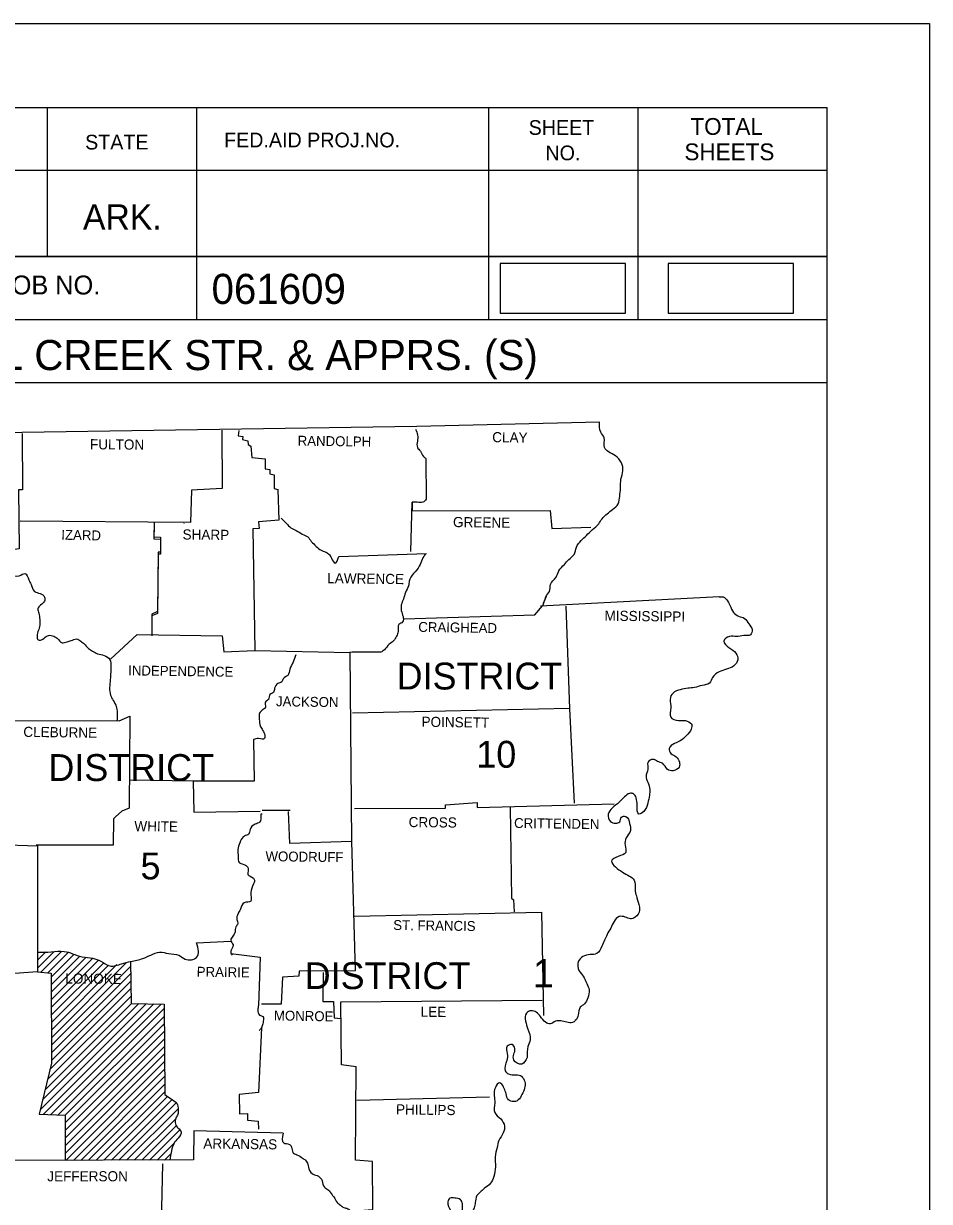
# Model space of a CAD drawing. Extents: x 1367863 to 1368197, y 380048 to 380261.
# Drawn here: x 1368154.6 to 1368196.7, y 380206.7 to 380261.4 of the extents above; entities that cross this region are included whole.
import ezdxf

# ---------------------------------------------------------------- set-up
doc = ezdxf.new("R2010")
doc.units = 0
for name, color, linetype in [('R_Border', 7, 'Continuous'), ('R_Dimension', 7, 'Continuous'), ('R_No Plot', 7, 'Continuous')]:
    doc.layers.add(name, color=color, linetype=linetype)

msp = doc.modelspace()

# ---------------------------------------------------------------- linework, layer by layer
at = {"layer": 'R_Border'}
for p, q in [((1367875.8, 380257.536), (1368191.969, 380257.536)), ((1368155.71, 380257.536), (1368155.71, 380250.596)), ((1368162.65, 380257.536), (1368162.65, 380247.657)), ((1368176.229, 380257.536), (1368176.229, 380247.657)), ((1368183.169, 380257.536), (1368183.169, 380247.657)), ((1368191.969, 380052.084), (1368191.969, 380257.536)), ((1368191.969, 380254.596), (1368148.87, 380254.596)), ((1368191.969, 380254.616), (1368191.969, 380254.616)), ((1368191.969, 380250.596), (1368148.87, 380250.596)), ((1368151.83, 380250.596), (1368191.969, 380250.596)), ((1368191.969, 380247.657), (1368109.712, 380247.657)), ((1368148.87, 380244.737), (1368191.969, 380244.737)), ((1368173.305, 380241.212), (1368173.325, 380239.319)), ((1368178.784, 380234.487), (1368178.924, 380234.806)), ((1368178.754, 380234.357), (1368178.884, 380234.766)), ((1368165.694, 380224.863), (1368166.999, 380224.863))]:
    msp.add_line(p, q, dxfattribs=at)
for points in [[(1368176.759, 380247.97), (1368182.592, 380247.97), (1368182.592, 380250.28), (1368176.759, 380250.28)], [(1368184.57, 380247.97), (1368190.404, 380247.97), (1368190.404, 380250.28), (1368184.57, 380250.28)]]:
    msp.add_lwpolyline(points, close=True, dxfattribs=at)
for points in [[(1368121.261, 380242.407), (1368138.984, 380242.397), (1368154.536, 380242.437), (1368172.886, 380242.716), (1368181.384, 380242.915)], [(1368163.821, 380242.527), (1368163.841, 380239.817), (1368162.416, 380239.737), (1368162.376, 380238.243), (1368154.446, 380238.293)], [(1368164.608, 380242.517), (1368164.578, 380242.258), (1368164.797, 380242.228), (1368164.787, 380242.088), (1368165.036, 380242.038), (1368165.056, 380241.859), (1368165.175, 380241.789), (1368165.215, 380241.261), (1368165.833, 380241.192), (1368165.833, 380240.723), (1368166.062, 380240.694), (1368166.062, 380240.504), (1368166.261, 380240.454), (1368166.251, 380239.817), (1368166.431, 380239.777), (1368166.471, 380238.342), (1368165.534, 380238.263), (1368165.554, 380237.954), (1368165.265, 380237.944), (1368165.365, 380232.285), (1368169.778, 380232.186), (1368169.858, 380223.399), (1368166.979, 380223.319), (1368166.919, 380224.803)], [(1368154.536, 380242.367), (1368154.556, 380239.757), (1368154.376, 380239.747), (1368154.406, 380237.017), (1368153.639, 380236.908), (1368153.699, 380236.171), (1368153.968, 380235.832), (1368153.948, 380234.975), (1368152.453, 380234.915), (1368152.404, 380233.58), (1368151.039, 380233.531), (1368150.979, 380231.917), (1368151.049, 380231.777), (1368151.089, 380229.197), (1368153.43, 380229.037), (1368153.4, 380223.269), (1368155.263, 380223.209), (1368155.263, 380217.342), (1368153.788, 380217.232), (1368153.679, 380215.937), (1368151.218, 380215.927)], [(1368172.617, 380236.888), (1368172.677, 380239.179), (1368172.677, 380238.771), (1368179.083, 380238.801), (1368179.173, 380237.954), (1368180.976, 380238.014)], [(1368160.682, 380238.213), (1368160.663, 380237.575), (1368160.971, 380237.555), (1368160.981, 380236.858), (1368160.872, 380236.858), (1368160.832, 380234.098), (1368160.573, 380233.979), (1368160.573, 380233.062)], [(1368160.682, 380238.113), (1368160.663, 380237.476), (1368160.971, 380237.456), (1368160.981, 380236.758), (1368160.872, 380236.758), (1368160.832, 380233.999), (1368160.573, 380233.889), (1368160.573, 380232.963)], [(1368162.057, 380238.193), (1368162.067, 380238.203)], [(1368169.26, 380236.649), (1368173.335, 380236.788)], [(1368172.289, 380233.75), (1368178.376, 380233.949), (1368178.734, 380234.367)], [(1368186.953, 380234.776), (1368178.635, 380234.347)], [(1368179.81, 380234.347), (1368179.99, 380229.595), (1368180.209, 380225.182)], [(1368158.65, 380231.887), (1368159.895, 380233.022), (1368163.841, 380232.963), (1368163.92, 380232.225), (1368165.355, 380232.285)], [(1368171.213, 380232.206), (1368169.878, 380232.206), (1368169.778, 380232.186)], [(1368179.99, 380229.595), (1368169.898, 380229.366)], [(1368153.43, 380229.037), (1368159.059, 380229.008), (1368159.547, 380229.237), (1368159.517, 380224.953), (1368159.178, 380224.813), (1368158.889, 380224.554), (1368158.79, 380224.465), (1368158.78, 380223.229), (1368155.193, 380223.229)], [(1368165.305, 380228.141), (1368165.335, 380226.218), (1368162.486, 380226.208), (1368159.557, 380226.258)], [(1368162.486, 380226.208), (1368162.525, 380224.764), (1368165.604, 380224.823)], [(1368169.987, 380224.933), (1368174.221, 380224.953), (1368174.231, 380225.112), (1368175.696, 380225.212), (1368175.696, 380224.983), (1368182.072, 380225.162)], [(1368177.23, 380224.983), (1368177.29, 380220.769), (1368177.389, 380220.699), (1368177.419, 380220.131)], [(1368165.694, 380224.684), (1368165.634, 380224.674)], [(1368169.858, 380223.399), (1368170.017, 380217.391), (1368167.417, 380217.381), (1368167.407, 380217.142), (1368166.65, 380217.093), (1368166.58, 380215.847), (1368165.664, 380215.847)], [(1368169.987, 380219.942), (1368178.685, 380220.121)], [(1368178.685, 380220.121), (1368178.774, 380215.319)], [(1368162.655, 380218.696), (1368164.249, 380218.776)], [(1368159.587, 380217.84), (1368159.606, 380215.877), (1368161.151, 380215.847), (1368161.171, 380211.643)], [(1368164.249, 380218.198), (1368165.614, 380218.029), (1368165.534, 380215.787)], [(1368155.263, 380217.342), (1368155.891, 380217.292), (1368155.91, 380213.108), (1368155.333, 380210.727), (1368156.548, 380210.677), (1368156.538, 380208.583)], [(1368168.533, 380217.322), (1368168.523, 380215.967), (1368169.021, 380215.967), (1368169.041, 380215.21), (1368169.36, 380215.18)], [(1368169.987, 380206.243), (1368170.844, 380206.303), (1368170.834, 380208.525), (1368170.037, 380208.585), (1368170.077, 380212.928), (1368169.39, 380213.028), (1368169.36, 380215.957), (1368178.714, 380216.027)], [(1368165.664, 380214.741), (1368165.524, 380211.743), (1368164.628, 380211.643), (1368164.648, 380210.746), (1368165.016, 380210.766), (1368165.026, 380210.458), (1368165.514, 380210.398), (1368165.524, 380210.039)], [(1368170.097, 380211.384), (1368176.274, 380211.543)], [(1368166.67, 380209.84), (1368162.525, 380209.949), (1368162.506, 380208.604), (1368154.117, 380208.575)], [(1368161.071, 380208.425), (1368160.981, 380204.301), (1368162.506, 380204.171)]]:
    msp.add_lwpolyline(points, dxfattribs=at)
for points in [[(1368172.827, 380242.576), (1368172.926, 380242.297), (1368172.916, 380242.009), (1368172.916, 380241.73), (1368173.056, 380241.55), (1368173.195, 380241.311), (1368173.305, 380241.212)], [(1368178.874, 380234.716), (1368178.884, 380234.766), (1368179.053, 380235.025), (1368179.103, 380235.354), (1368179.362, 380235.692), (1368179.492, 380235.991), (1368179.751, 380236.29), (1368179.95, 380236.509), (1368180.199, 380236.748), (1368180.308, 380237.087), (1368180.538, 380237.396), (1368180.777, 380237.635), (1368181.056, 380237.904), (1368181.345, 380238.173), (1368181.504, 380238.412), (1368181.733, 380238.641), (1368181.992, 380238.841), (1368182.251, 380239.109), (1368182.321, 380239.448), (1368182.361, 380239.827), (1368182.381, 380240.255), (1368182.47, 380240.634), (1368182.401, 380241.012), (1368182.122, 380241.331), (1368181.803, 380241.52), (1368181.614, 380241.72), (1368181.594, 380242.178), (1368181.444, 380242.437), (1368181.384, 380242.915)], [(1368173.325, 380239.319), (1368173.175, 380239.179), (1368172.906, 380239.179), (1368172.677, 380239.179)], [(1368166.59, 380238.442), (1368166.829, 380238.193), (1368167.038, 380237.984), (1368167.278, 380237.864), (1368167.566, 380237.695), (1368167.816, 380237.565), (1368167.985, 380237.356), (1368168.214, 380237.127), (1368168.443, 380236.948), (1368168.802, 380236.768), (1368168.921, 380236.579), (1368169.091, 380236.35), (1368169.26, 380236.649)], [(1368173.295, 380236.778), (1368173.135, 380236.519), (1368173.006, 380236.21), (1368172.737, 380235.862), (1368172.538, 380235.513), (1368172.508, 380235.284), (1368172.358, 380234.985), (1368172.269, 380234.676), (1368172.169, 380234.407), (1368172.169, 380234.138), (1368172.249, 380233.859), (1368172.229, 380233.61), (1368172.06, 380233.491), (1368172.02, 380233.172), (1368171.95, 380232.953), (1368171.81, 380232.734), (1368171.601, 380232.574), (1368171.382, 380232.315), (1368171.213, 380232.206)], [(1368153.968, 380235.832), (1368154.406, 380235.762), (1368154.665, 380235.862), (1368154.854, 380235.573), (1368154.954, 380235.354), (1368155.113, 380235.035), (1368155.382, 380234.935), (1368155.582, 380234.766), (1368155.582, 380234.577), (1368155.402, 380234.397), (1368155.273, 380234.228), (1368155.313, 380234.019), (1368155.362, 380233.73), (1368155.362, 380233.461), (1368155.293, 380233.202), (1368155.233, 380232.973), (1368155.293, 380232.783), (1368155.502, 380232.813), (1368155.721, 380232.973), (1368155.95, 380232.973), (1368156.169, 380232.853), (1368156.399, 380232.644), (1368156.628, 380232.694), (1368156.817, 380232.743), (1368157.076, 380232.823), (1368157.265, 380232.724), (1368157.425, 380232.594), (1368157.624, 380232.385), (1368157.813, 380232.255), (1368158.052, 380232.136), (1368158.351, 380232.056), (1368158.62, 380231.867), (1368158.67, 380231.548), (1368158.66, 380231.279), (1368158.64, 380230.94), (1368158.61, 380230.562), (1368158.65, 380230.203), (1368158.77, 380229.964), (1368158.919, 380229.675), (1368158.959, 380229.416), (1368158.949, 380228.998)], [(1368186.953, 380234.776), (1368187.073, 380234.786), (1368187.442, 380234.387), (1368187.611, 380234.059), (1368187.85, 380233.879), (1368188.129, 380233.78), (1368188.328, 380233.521), (1368188.478, 380233.252), (1368188.398, 380233.012), (1368188.089, 380232.983), (1368187.75, 380232.933), (1368187.422, 380232.943), (1368187.163, 380232.724), (1368187.402, 380232.425), (1368187.721, 380232.156), (1368187.81, 380231.857), (1368187.631, 380231.568), (1368187.282, 380231.418), (1368186.943, 380231.289), (1368186.635, 380231.03), (1368186.495, 380230.771), (1368186.156, 380230.661), (1368185.798, 380230.562), (1368185.499, 380230.532), (1368185.14, 380230.462), (1368184.802, 380230.303), (1368184.662, 380230.014), (1368184.702, 380229.615), (1368184.692, 380229.187), (1368185.061, 380229.037), (1368185.379, 380229.028), (1368185.678, 380228.868)], [(1368167.268, 380232.086), (1368167.138, 380231.747), (1368166.989, 380231.418), (1368166.889, 380231.13), (1368166.68, 380230.97), (1368166.61, 380230.821), (1368166.431, 380230.751), (1368166.281, 380230.532), (1368166.222, 380230.333), (1368166.062, 380230.243), (1368165.992, 380230.004), (1368165.843, 380229.874), (1368165.853, 380229.655), (1368165.694, 380229.506), (1368165.564, 380229.326), (1368165.564, 380229.087), (1368165.614, 380228.768), (1368165.723, 380228.579), (1368165.823, 380228.34), (1368165.813, 380228.191), (1368165.534, 380228.191), (1368165.305, 380228.141)], [(1368185.678, 380228.868), (1368185.648, 380228.629), (1368185.419, 380228.32), (1368185.14, 380228.081), (1368184.871, 380227.962), (1368184.622, 380227.722), (1368184.702, 380227.493), (1368184.941, 380227.344), (1368185.1, 380227.095), (1368185.08, 380226.866), (1368184.811, 380226.696), (1368184.533, 380226.766), (1368184.323, 380227.035), (1368184.084, 380227.125), (1368183.875, 380227.224), (1368183.636, 380227.085), (1368183.636, 380226.766), (1368183.546, 380226.427), (1368183.626, 380226.168), (1368183.716, 380225.82), (1368183.706, 380225.561), (1368183.626, 380225.182), (1368183.437, 380224.803), (1368183.217, 380224.684), (1368183.128, 380225.092), (1368183.088, 380225.431), (1368182.948, 380225.63), (1368182.779, 380225.64), (1368182.55, 380225.481), (1368182.291, 380225.232), (1368181.972, 380224.953), (1368181.793, 380224.684), (1368181.892, 380224.335), (1368182.132, 380224.256), (1368182.321, 380224.315), (1368182.411, 380224.534), (1368182.6, 380224.574), (1368182.779, 380224.236)], [(1368165.634, 380224.674), (1368165.584, 380224.305), (1368165.375, 380224.206), (1368165.136, 380223.967), (1368165.076, 380223.747), (1368164.877, 380223.658), (1368164.697, 380223.429), (1368164.578, 380223.11), (1368164.578, 380222.781), (1368164.648, 380222.412), (1368164.926, 380222.313), (1368165.056, 380222.094), (1368165.036, 380221.865), (1368165.295, 380221.705), (1368165.345, 380221.576), (1368165.295, 380221.436), (1368165.175, 380221.028), (1368165.185, 380220.759), (1368165.166, 380220.639), (1368164.867, 380220.559), (1368164.697, 380220.261), (1368164.578, 380220.051), (1368164.528, 380219.782), (1368164.568, 380219.583), (1368164.478, 380219.434), (1368164.438, 380219.205), (1368164.339, 380219.005), (1368164.239, 380218.816), (1368164.349, 380218.597), (1368164.309, 380218.447), (1368164.249, 380218.198), (1368164.299, 380218.129)], [(1368182.779, 380224.236), (1368182.819, 380223.917), (1368182.63, 380223.578), (1368182.57, 380223.229), (1368182.6, 380222.891), (1368182.251, 380222.711), (1368181.942, 380222.492), (1368182.122, 380222.223), (1368182.45, 380221.984), (1368182.779, 380221.795), (1368182.988, 380221.615), (1368183.038, 380221.167), (1368183.098, 380220.878), (1368183.208, 380220.48), (1368183.247, 380220.211), (1368183.048, 380219.882), (1368182.819, 380219.812), (1368182.58, 380219.892), (1368182.291, 380219.912), (1368182.062, 380219.693), (1368181.902, 380219.384), (1368181.733, 380219.075), (1368181.614, 380218.816), (1368181.494, 380218.537), (1368181.255, 380218.198), (1368180.956, 380218.149), (1368180.607, 380218.059), (1368180.398, 380217.82), (1368180.428, 380217.411), (1368180.627, 380217.142), (1368180.787, 380216.804), (1368180.896, 380216.505), (1368180.836, 380216.136), (1368180.687, 380215.857), (1368180.488, 380215.698), (1368180.398, 380215.339), (1368180.259, 380215.08), (1368180.129, 380214.99), (1368179.86, 380215.01), (1368179.581, 380215.07), (1368179.332, 380215.05), (1368179.103, 380214.931), (1368178.874, 380215), (1368178.635, 380215.269), (1368178.436, 380215.469), (1368178.216, 380215.538), (1368177.987, 380215.419), (1368177.947, 380215.06), (1368178.057, 380214.682), (1368178.157, 380214.183), (1368178.057, 380213.875), (1368178.017, 380213.367)], [(1368155.283, 380218.258), (1368155.891, 380218.278), (1368156.498, 380218.298), (1368156.887, 380218.188), (1368157.325, 380218.049), (1368157.833, 380217.979), (1368158.202, 380217.84), (1368158.62, 380217.621), (1368159.168, 380217.72), (1368159.597, 380217.83), (1368160.154, 380217.969), (1368160.523, 380218.129), (1368160.931, 380218.258), (1368161.35, 380218.198), (1368161.828, 380218.119), (1368162.117, 380217.939), (1368162.655, 380218.019), (1368162.655, 380218.696)], [(1368165.534, 380215.787), (1368165.494, 380215.568), (1368165.584, 380215.339), (1368165.733, 380215.269), (1368165.753, 380215.05), (1368165.704, 380214.831), (1368165.664, 380214.741), (1368165.564, 380214.612)], [(1368178.017, 380213.367), (1368177.768, 380213.058), (1368177.399, 380213.247), (1368177.399, 380213.516), (1368177.449, 380213.785), (1368177.32, 380213.964), (1368177.091, 380213.885), (1368177.091, 380213.546), (1368177.071, 380213.217), (1368177.001, 380212.749), (1368177.15, 380212.599), (1368177.509, 380212.56), (1368177.758, 380212.49), (1368177.907, 380212.241), (1368177.898, 380211.932), (1368177.778, 380211.643), (1368177.609, 380211.394), (1368177.33, 380211.314), (1368177.11, 380211.454), (1368177.021, 380211.743), (1368176.921, 380211.992), (1368176.742, 380212.181), (1368176.543, 380211.972), (1368176.493, 380211.583), (1368176.513, 380211.255), (1368176.513, 380210.806), (1368176.792, 380210.507), (1368176.971, 380210.169), (1368176.911, 380209.86), (1368176.702, 380209.501), (1368176.622, 380209.182), (1368176.533, 380208.754), (1368176.543, 380208.286), (1368176.463, 380207.827), (1368176.314, 380207.519), (1368176.025, 380207.27), (1368175.835, 380207.1), (1368175.686, 380206.941), (1368175.606, 380206.612), (1368175.556, 380206.383), (1368175.347, 380206.104), (1368175.178, 380206.084), (1368175.048, 380206.194), (1368175.008, 380206.383), (1368175.008, 380206.562), (1368174.919, 380206.751), (1368174.65, 380206.831), (1368174.431, 380206.821), (1368174.331, 380206.662), (1368174.47, 380206.233), (1368174.52, 380205.964), (1368174.451, 380205.586), (1368174.49, 380205.546), (1368174.102, 380205.337), (1368173.783, 380205.307), (1368173.514, 380205.227), (1368173.265, 380205.068), (1368173.145, 380204.819), (1368172.966, 380204.63), (1368172.817, 380204.44), (1368172.607, 380204.351)], [(1368161.171, 380211.643), (1368161.44, 380211.454), (1368161.729, 380211.235), (1368161.798, 380210.936), (1368161.778, 380210.727), (1368161.689, 380210.557), (1368161.669, 380210.278), (1368161.798, 380210.079), (1368161.928, 380209.92), (1368161.798, 380209.621), (1368161.589, 380209.352), (1368161.489, 380209.043), (1368161.41, 380208.585)], [(1368166.67, 380209.84), (1368166.7, 380209.392), (1368166.969, 380209.322), (1368167.068, 380209.202), (1368167.128, 380208.953), (1368167.317, 380208.844), (1368167.566, 380208.694), (1368167.716, 380208.585), (1368167.826, 380208.405), (1368167.895, 380208.116), (1368168.075, 380207.937), (1368168.314, 380207.847), (1368168.483, 380207.638), (1368168.593, 380207.339), (1368168.772, 380207.21), (1368168.951, 380206.981), (1368169.031, 380206.881), (1368169.19, 380206.622), (1368169.34, 380206.492), (1368169.449, 380206.413), (1368169.629, 380206.353), (1368169.848, 380206.214), (1368169.987, 380205.994), (1368169.987, 380205.835), (1368169.938, 380205.576), (1368169.888, 380205.317), (1368169.868, 380205.018), (1368169.848, 380204.759), (1368169.948, 380204.54), (1368169.888, 380204.211), (1368169.778, 380204.032), (1368169.768, 380203.793), (1368169.738, 380203.434), (1368169.688, 380203.225), (1368169.599, 380202.886), (1368169.449, 380202.707)]]:
    msp.add_spline(points, degree=3, dxfattribs=at)
at = {"layer": 'R_Dimension'}
for p, q in [((1368155.267, 380217.535), (1368156.014, 380218.282)), ((1368155.275, 380217.897), (1368155.648, 380218.27)), ((1368155.415, 380217.33), (1368156.379, 380218.294)), ((1368155.742, 380217.304), (1368156.682, 380218.243)), ((1368155.891, 380217.099), (1368156.953, 380218.161)), ((1368155.893, 380216.747), (1368157.225, 380218.079)), ((1368155.895, 380216.395), (1368157.522, 380218.022)), ((1368155.896, 380216.043), (1368157.832, 380217.979)), ((1368155.898, 380215.691), (1368158.089, 380217.882)), ((1368155.9, 380215.34), (1368158.332, 380217.772)), ((1368155.901, 380214.988), (1368158.564, 380217.65)), ((1368155.903, 380214.636), (1368158.947, 380217.68)), ((1368155.905, 380214.284), (1368159.4, 380217.78)), ((1368155.907, 380213.932), (1368159.59, 380217.615)), ((1368155.908, 380213.58), (1368159.593, 380217.265)), ((1368155.91, 380213.228), (1368159.596, 380216.915)), ((1368155.723, 380212.334), (1368159.603, 380216.215)), ((1368155.836, 380212.801), (1368159.6, 380216.565)), ((1368155.383, 380210.934), (1368160.313, 380215.863)), ((1368155.496, 380211.4), (1368159.966, 380215.87)), ((1368155.522, 380210.719), (1368160.66, 380215.857)), ((1368155.609, 380211.867), (1368159.619, 380215.877)), ((1368155.861, 380210.705), (1368161.006, 380215.85)), ((1368156.201, 380210.691), (1368161.152, 380215.642)), ((1368156.541, 380210.677), (1368161.153, 380215.29)), ((1368156.545, 380209.974), (1368161.157, 380214.586)), ((1368156.546, 380210.329), (1368161.155, 380214.938)), ((1368156.543, 380209.619), (1368161.158, 380214.234)), ((1368156.539, 380208.908), (1368161.162, 380213.53)), ((1368156.541, 380209.263), (1368161.16, 380213.882)), ((1368156.568, 380208.583), (1368161.163, 380213.178)), ((1368156.922, 380208.583), (1368161.165, 380212.827)), ((1368157.275, 380208.583), (1368161.167, 380212.475)), ((1368157.629, 380208.584), (1368161.168, 380212.123)), ((1368157.983, 380208.584), (1368161.17, 380211.771)), ((1368158.336, 380208.584), (1368161.301, 380211.548)), ((1368158.69, 380208.584), (1368161.505, 380211.398)), ((1368159.044, 380208.584), (1368161.709, 380211.249)), ((1368159.397, 380208.584), (1368161.789, 380210.976)), ((1368159.751, 380208.584), (1368161.686, 380210.519)), ((1368160.105, 380208.584), (1368161.723, 380210.203)), ((1368160.458, 380208.584), (1368161.871, 380209.998)), ((1368160.812, 380208.584), (1368161.604, 380209.376)), ((1368161.166, 380208.585), (1368161.461, 380208.88))]:
    msp.add_line(p, q, dxfattribs=at)
at = {"layer": 'R_No Plot'}
for p in [(1367863.388, 380261.431), (1367863.4, 380261.431)]:
    msp.add_line(p, (1368196.721, 380261.431), dxfattribs=at)
msp.add_lwpolyline([(1367863.393, 380261.431), (1368196.721, 380261.431), (1368196.721, 380048.101), (1367863.393, 380048.101)], close=True, dxfattribs=at)

# ---------------------------------------------------------------- texts
at = {"layer": 'R_Border'}
for s, height, rotation, p in [('SHEET', 0.684, 360, (1368178.089, 380256.256)), ('TOTAL', 0.7819, 360, (1368185.609, 380256.256)), ('STATE', 0.684, 360, (1368157.47, 380255.576)), ('FED.AID PROJ.NO.', 0.68398, 360, (1368163.93, 380255.676)), ('NO.', 0.684, 360, (1368178.869, 380255.076)), ('SHEETS', 0.7819, 360, (1368185.329, 380255.076)), ('ARK.', 1.1722, 360, (1368157.37, 380251.856)), ('JOB NO.', 0.8792, 360, (1368153.47, 380248.837)), ('061609', 1.4, 360, (1368163.346, 380248.396)), ('MILL CREEK STR. & APPRS. (S)', 1.39995, 360, (1368150.427, 380245.32)), ('FULTON', 0.4711, 359.4996, (1368157.694, 380241.64)), ('RANDOLPH', 0.4603, 359.2583, (1368167.347, 380241.809)), ('CLAY', 0.4711, 359.2258, (1368176.393, 380241.969)), ('GREENE', 0.4713, 359.2361, (1368174.57, 380238.024)), ('IZARD', 0.4601, 358.9258, (1368156.359, 380237.436)), ('SHARP', 0.4711, 359.3905, (1368161.997, 380237.446)), ('LAWRENCE', 0.4713, 359.2678, (1368168.722, 380235.413)), ('MISSISSIPPI', 0.47114, 359.3097, (1368181.614, 380233.67)), ('CRAIGHEAD', 0.4603, 359.1159, (1368172.956, 380233.152)), ('INDEPENDENCE', 0.46015, 359.2187, (1368159.467, 380231.13)), ('JACKSON', 0.4601, 359.1352, (1368166.341, 380229.695)), ('POINSETT', 0.4711, 359.1987, (1368173.106, 380228.739)), ('CLEBURNE', 0.4711, 359.2535, (1368154.595, 380228.27)), ('CROSS', 0.4711, 359.3839, (1368172.508, 380224.076)), ('CRITTENDEN', 0.4603, 359.213, (1368177.409, 380224.036)), ('WHITE', 0.4713, 359.3139, (1368159.756, 380223.887)), ('WOODRUFF', 0.4601, 359.2748, (1368165.853, 380222.492)), ('ST. FRANCIS', 0.46015, 359.2216, (1368171.791, 380219.294)), ('LONOKE', 0.4713, 359.4974, (1368156.548, 380216.804)), ('PRAIRIE', 0.4603, 359.2116, (1368162.655, 380217.122)), ('LEE', 0.4713, 359.4327, (1368173.066, 380215.259)), ('MONROE', 0.4601, 359.0331, (1368166.241, 380215.09)), ('PHILLIPS', 0.4711, 359.3179, (1368171.92, 380210.717)), ('ARKANSAS', 0.4711, 359.2678, (1368162.964, 380209.133))]:
    msp.add_text(s, height=height, rotation=rotation, dxfattribs=at).set_placement(p)
for s, height, p in [('DISTRICT', 1.2493, (1368171.95, 380230.472)), ('10', 1.2493, (1368175.656, 380226.836)), ('DISTRICT', 1.2493, (1368155.761, 380226.218)), ('5', 1.249, (1368160.045, 380221.645)), ('DISTRICT', 1.2493, (1368167.676, 380216.545)), ('1', 1.315, (1368178.286, 380216.624)), ('JEFFERSON', 0.4712, (1368155.711, 380207.608))]:
    msp.add_text(s, height=height, dxfattribs=at).set_placement(p)

doc.saveas('drawing.dxf')
